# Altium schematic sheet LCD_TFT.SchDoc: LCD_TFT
size A3; DocumentNumber: MB1144; Revision: C-02; SheetNumber: 11; SheetTotal: 25; PageSetup: Record=PageOptions|CenterHorizontal=True|CenterVertical=True|PrintScale=1.01|XCorrection=1.00|YCorrection=1.00|PrintKind=1|BorderSize=5000000|LeftOffset=0|BottomOffset=0|Orientation=2|PaperLength=1000|PaperWidth=1000|Scale=100|PaperSource=15|PrintQuality=600|MediaType=1|DitherType=10|PaperKind=A3|PrintScaleMode=1; Project: STM32L476G-EVAL
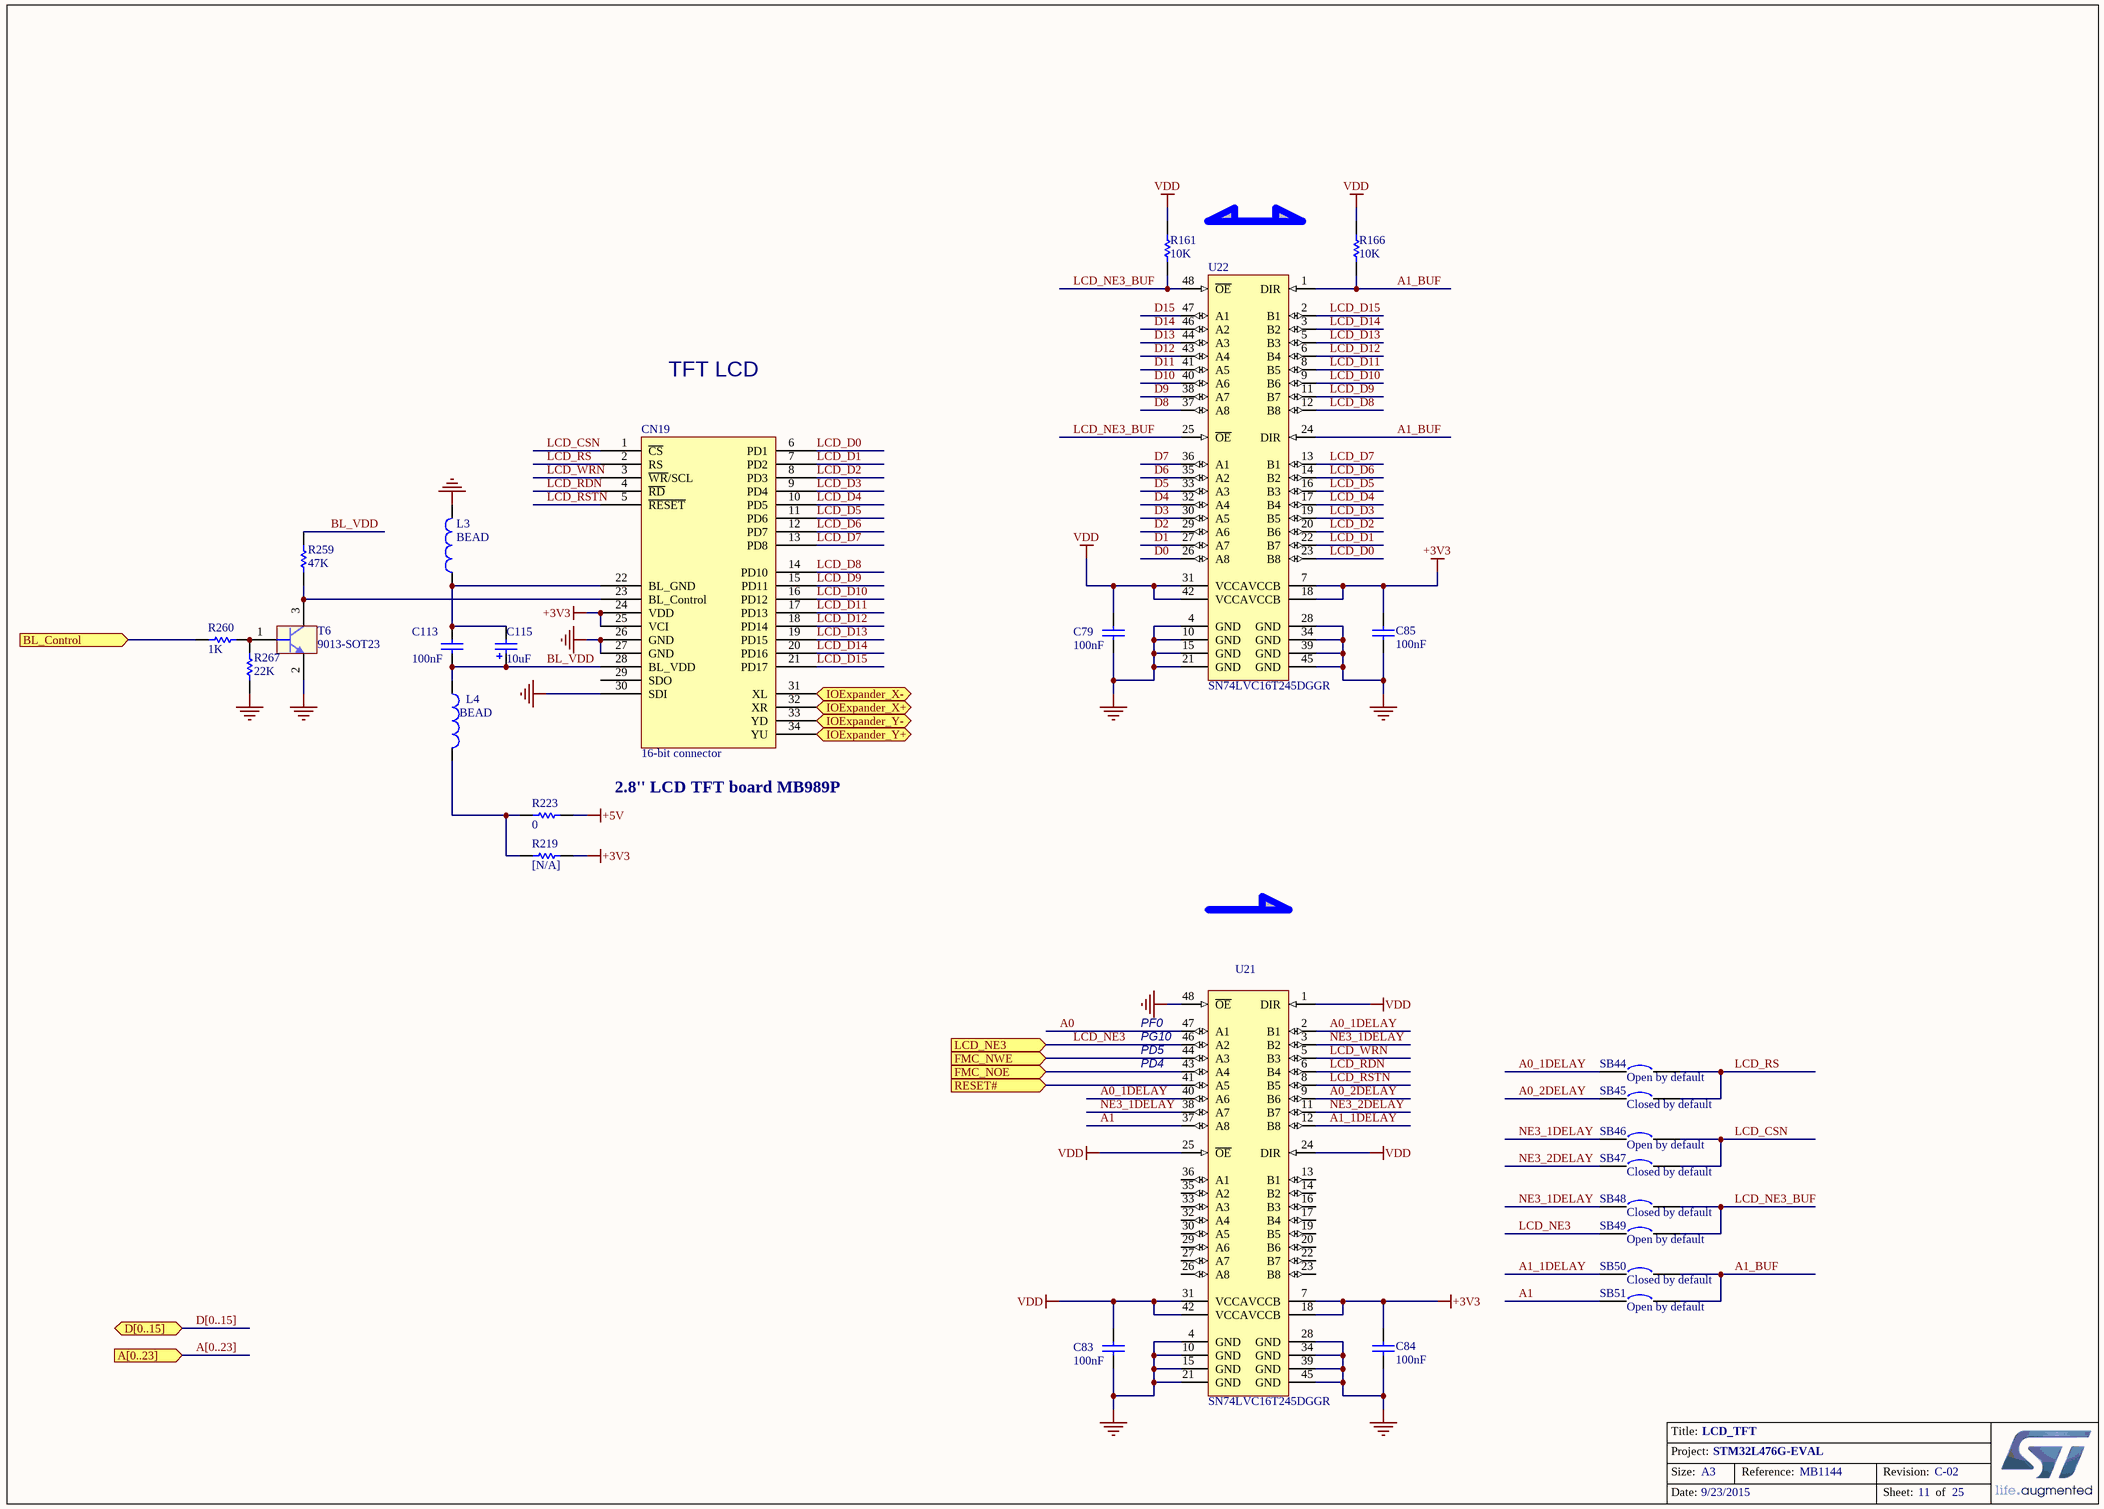
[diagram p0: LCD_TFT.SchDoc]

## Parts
C79  100nF  [0402C]
C83  100nF  [0402C]
C84  100nF  [0402C]
C85  100nF  [0402C]
C113  100nF  [0402C]
C115  10uF  [TAN-A]
CN19  16-bit connector  [HDR_2X17_2R54]
L3  BEAD  [0603L]
L4  BEAD  [0603L]
R161  10K  [0402R]
R166  10K  [0402R]
R219  [N/A]  [0603R]
R223  0  [0603R]
R259  47K  [0402R]
R260  1K  [0402R]
R267  22K  [0402R]
SB44  Open by default  [SB_0603]
SB45  Closed by default  [SB_0603]
SB46  Open by default  [SB_0603]
SB47  Closed by default  [SB_0603]
SB48  Closed by default  [SB_0603]
SB49  Open by default  [SB_0603]
SB50  Closed by default  [SB_0603]
SB51  Open by default  [SB_0603]
T6  9013-SOT23  [SOT-23]
U21  SN74LVC16T245DGGR  [TSSOP48_0R5_12R5X8R1]
U22  SN74LVC16T245DGGR  [TSSOP48_0R5_12R5X8R1]

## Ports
A[0..23] (in), BL_Control (in), D[0..15] (bidir), FMC_NOE (in), FMC_NWE (in), IOExpander_X+ (bidir), IOExpander_X- (bidir), IOExpander_Y+ (bidir), IOExpander_Y- (bidir), LCD_NE3 (in), RESET# (in)

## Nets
+3V3: C84.1 C85.1 CN19.24(VDD) CN19.25(VCI) R219.1 U21.7(VCCB) U21.18(VCCB) U22.7(VCCB) U22.18(VCCB)
+5V: R223.1
GND: C79.2 C83.2 C84.2 C85.2 CN19.26(GND) CN19.27(GND) CN19.30(SDI) L3.2 R267.2 T6.2(E) U21.4(GND) U21.10(GND) U21.15(GND) U21.21(GND) U21.28(GND) U21.34(GND) U21.39(GND) U21.45(GND) U21.48(~{OE}) U22.4(GND) U22.10(GND) U22.15(GND) U22.21(GND) U22.28(GND) U22.34(GND) U22.39(GND) U22.45(GND)
VDD: C79.1 C83.1 R161.1 R166.1 U21.1(DIR) U21.24(DIR) U21.25(~{OE}) U21.31(VCCA) U21.42(VCCA) U22.31(VCCA) U22.42(VCCA)
A0: U21.47(A1)
A0_1DELAY: SB44.1 U21.2(B1) U21.40(A6)
A0_2DELAY: SB45.1 U21.9(B6)
A1: SB51.1 U21.37(A8)
A1_1DELAY: SB50.1 U21.12(B8)
A1_BUF: R166.2 SB50.2 SB51.2 U22.1(DIR) U22.24(DIR)
BL_Control: R260.1 ; port BL_Control
BL_VDD: C113.2 C115.1 CN19.28(BL_VDD) L4.1 R259.1
D0: U22.26(A8)
D1: U22.27(A7)
D2: U22.29(A6)
D3: U22.30(A5)
D4: U22.32(A4)
D5: U22.33(A3)
D6: U22.35(A2)
D7: U22.36(A1)
D8: U22.37(A8)
D9: U22.38(A7)
D10: U22.40(A6)
D11: U22.41(A5)
D12: U22.43(A4)
D13: U22.44(A3)
D14: U22.46(A2)
D15: U22.47(A1)
FMC_NOE: U21.43(A4) ; port FMC_NOE
FMC_NWE: U21.44(A3) ; port FMC_NWE
IOExpander_X+: CN19.32(XR) ; port IOExpander_X+
IOExpander_X-: CN19.31(XL) ; port IOExpander_X-
IOExpander_Y+: CN19.34(YU) ; port IOExpander_Y+
IOExpander_Y-: CN19.33(YD) ; port IOExpander_Y-
LCD_CSN: CN19.1(~{CS}) SB46.2 SB47.2
LCD_D0: CN19.6(PD1) U22.23(B8)
LCD_D1: CN19.7(PD2) U22.22(B7)
LCD_D2: CN19.8(PD3) U22.20(B6)
LCD_D3: CN19.9(PD4) U22.19(B5)
LCD_D4: CN19.10(PD5) U22.17(B4)
LCD_D5: CN19.11(PD6) U22.16(B3)
LCD_D6: CN19.12(PD7) U22.14(B2)
LCD_D7: CN19.13(PD8) U22.13(B1)
LCD_D8: CN19.14(PD10) U22.12(B8)
LCD_D9: CN19.15(PD11) U22.11(B7)
LCD_D10: CN19.16(PD12) U22.9(B6)
LCD_D11: CN19.17(PD13) U22.8(B5)
LCD_D12: CN19.18(PD14) U22.6(B4)
LCD_D13: CN19.19(PD15) U22.5(B3)
LCD_D14: CN19.20(PD16) U22.3(B2)
LCD_D15: CN19.21(PD17) U22.2(B1)
LCD_NE3: SB49.1 U21.46(A2) ; port LCD_NE3
LCD_NE3_BUF: R161.2 SB48.2 SB49.2 U22.25(~{OE}) U22.48(~{OE})
LCD_RDN: CN19.4(~{RD}) U21.6(B4)
LCD_RS: CN19.2(RS) SB44.2 SB45.2
LCD_RSTN: CN19.5(~{RESET}) U21.8(B5)
LCD_WRN: CN19.3(~{WR}/SCL) U21.5(B3)
NE3_1DELAY: SB46.1 SB48.1 U21.3(B2) U21.38(A7)
NE3_2DELAY: SB47.1 U21.11(B7)
RESET#: U21.41(A5) ; port RESET#
NetC113_1: C113.1 C115.2 CN19.22(BL_GND) L3.1
NetCN19_23: CN19.23(BL_Control) R259.2 T6.3(C)
NetL4_2: L4.2 R219.2 R223.2
NetR260_2: R260.2 R267.1 T6.1(B)

Not connected (* = marked no-connect by the designer): CN19 29(SDO); U21 13(B1) 14(B2) 16(B3) 17(B4) 19(B5) 20(B6) 22(B7) 23(B8) 26(A8) 27(A7) 29(A6) 30(A5) 32(A4) 33(A3) 35(A2) 36(A1)

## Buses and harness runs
bus A[0..23] = port A[0..23]
bus D[0..15] = port D[0..15]

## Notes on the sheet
- TFT LCD
- 2.8'' LCD TFT board MB989P
- (near U21) PG10
- (near U21) PD5
- (near U21) PF0
- (near U21) PD4

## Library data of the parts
C79 C83-C85 = CAP: Capacitor; Value: 100pF; Ordered by: Subcon; ECCN_US/EU: NA
C113 = Cap: Capacitor; Value: 10nF; Ordered by: Subcon; ECCN_US/EU: NA
C115 = Cap Pol1: Polarized Capacitor (Radial); Ordered by: Subcon; ECCN_US/EU: NA
CN19 = ColorLCD_module_16bits: Female connector 2x17; Ordered by: Subcon; Comments: LCD TFT paralell; Assembly: with MB989P revB; ECCN_US/EU: NA
L3 L4 = Inductor: Value: 100uH; Ordered by: Subcon; ECCN_US/EU: NA
R161 R166 R267 = res1: Resistor; Value: 1K; Ordered by: Subcon; ECCN_US/EU: NA
R219 = Res1: Resistor; Value: 1K; Ordered by: Subcon; ECCN_US/EU: NA; Fitted: NO
R223 R259 = Res1: Resistor; Value: 1K; Ordered by: Subcon; ECCN_US/EU: NA
R260 = Res1: Resistor; Ordered by: Subcon; ECCN_US/EU: NA
SB44 SB46 SB49 SB51 = Circuit Breaker: Ordered by: Subcon; Comments: Solder bridge; Fitted: NO; ECCN_US/EU: NA
SB45 SB47 SB48 SB50 = Circuit Breaker: Ordered by: Subcon; Comments: Solder bridge; ECCN_US/EU: NA
T6 = 9013-SOT23: NPN Bipolar Transistor; Manuf_1: Taitron; Manuf_Part_1: MMBT9013; Description: NPN Bipolar Transistor, SOT-23 Footprint; Ordered by: Subcon; ECCN_US/EU: EAR99/NEC
U21 U22 = SN74LVC16T245: Manuf_1: TI; Ordered by: Subcon; ECCN_US/EU: EAR99/NEC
